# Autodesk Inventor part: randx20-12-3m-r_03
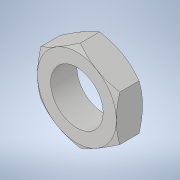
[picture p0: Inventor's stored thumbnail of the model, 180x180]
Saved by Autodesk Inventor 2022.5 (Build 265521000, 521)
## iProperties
Created: 2021-02
Part Number: randx20-12-3m-r_03
Material: 一般
Document SubType Name: Modeling
Designer: ImaoCorp
Density: 1 g/cm^3
Appearance: 既定
Author: ImaoCorp
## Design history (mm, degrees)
feature "randx20-12-3m-r_03"
node "ソリッド1"
